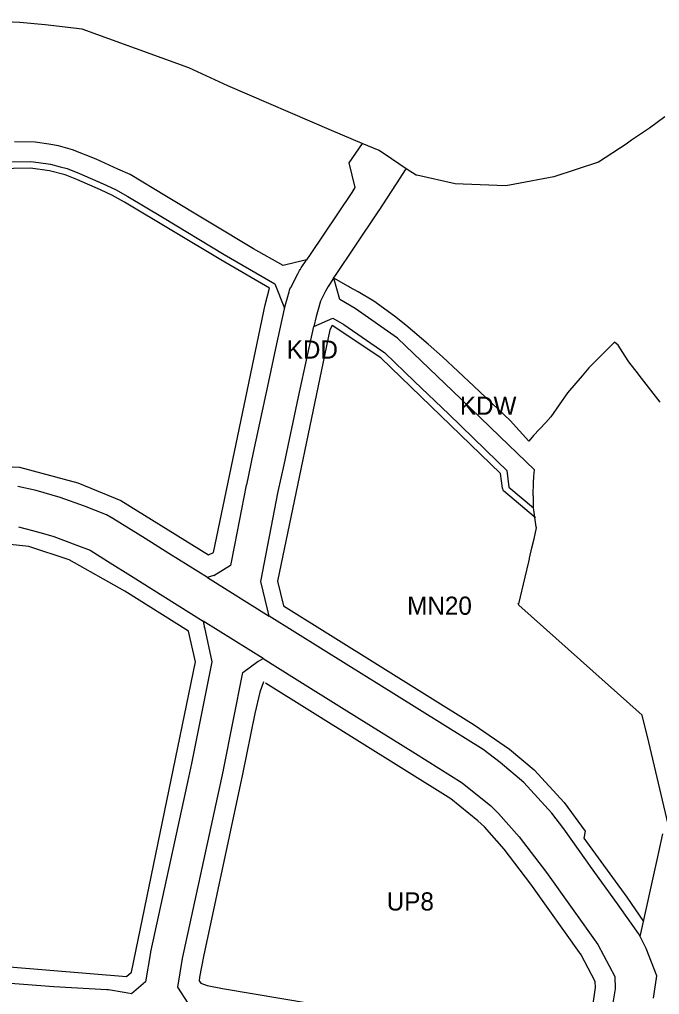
# Model space of a CAD drawing. Extents: x 7428080 to 7432143, y 5545880 to 5549217.
# Drawn here: x 7430729.6 to 7430925.4, y 5547441.7 to 5547739.8 of the extents above; entities that cross this region are included whole.
import ezdxf

# ---------------------------------------------------------------- set-up
doc = ezdxf.new("R2010")
doc.units = 0
for name, color, linetype in [('CZ_L_linie rozgraniczające tereny o różnym przeznaczeniu oraz różnych warunkach ich zabudowy i zagospodarowania', 7, 'Continuous'), ('CZ_L_maksymalne nieprzekraczalne linie zabudowy', 7, 'Continuous'), ('CZ_L_opisy_linie rozgraniczające tereny o różnym przeznaczeniu oraz różnych warunkach ich zabudowy i zagospodarowania', 7, 'Continuous')]:
    doc.layers.add(name, color=color, linetype=linetype)

msp = doc.modelspace()

# ---------------------------------------------------------------- linework, layer by layer
at = {"layer": 'CZ_L_linie rozgraniczające tereny o różnym przeznaczeniu oraz różnych warunkach ich zabudowy i zagospodarowania'}
for p, q in [((7430729.73, 5547738.83), (7430708.44, 5547739.76)), ((7430737.45, 5547738.17), (7430729.73, 5547738.83)), ((7430748.78, 5547736.77), (7430737.45, 5547738.17)), ((7430781.41, 5547725.02), (7430748.78, 5547736.77)), ((7430793.36, 5547719.53), (7430781.41, 5547725.02)), ((7430825.02, 5547705.84), (7430793.36, 5547719.53)), ((7430927.02, 5547710), (7430922.34, 5547706.55)), ((7430834.43, 5547701.88), (7430825.02, 5547705.84)), ((7430918.68, 5547704.09), (7430916.85, 5547702.86)), ((7430922.34, 5547706.55), (7430918.68, 5547704.09)), ((7430734.35, 5547702.22), (7430728.1, 5547702.36)), ((7430738.51, 5547701.68), (7430734.35, 5547702.22)), ((7430741.5, 5547701.1), (7430738.51, 5547701.68)), ((7430745.84, 5547699.95), (7430741.5, 5547701.1)), ((7430834.43, 5547701.88), (7430830.29, 5547695.93)), ((7430839.61, 5547699.7), (7430834.43, 5547701.88)), ((7430915.14, 5547701.62), (7430906.73, 5547696.19)), ((7430916.85, 5547702.86), (7430915.14, 5547701.62)), ((7430753.07, 5547697.04), (7430745.84, 5547699.95)), ((7430843.36, 5547697.14), (7430839.61, 5547699.7)), ((7430726.23, 5547696.23), (7430733.01, 5547696.31)), ((7430733.01, 5547696.31), (7430735.43, 5547696.03)), ((7430735.43, 5547696.03), (7430739.1, 5547695.5)), ((7430739.1, 5547695.5), (7430742.02, 5547694.75)), ((7430742.02, 5547694.75), (7430744.16, 5547694.17)), ((7430759.67, 5547694.03), (7430753.07, 5547697.04)), ((7430830.29, 5547695.93), (7430832.2, 5547688.37)), ((7430847.84, 5547694.08), (7430843.36, 5547697.14)), ((7430906.73, 5547696.19), (7430893.07, 5547691.66)), ((7430744.16, 5547694.17), (7430747.93, 5547692.68)), ((7430747.93, 5547692.68), (7430755.18, 5547689.56)), ((7430763.41, 5547692.39), (7430759.67, 5547694.03)), ((7430774.54, 5547685.65), (7430763.41, 5547692.39)), ((7430845.99, 5547691.22), (7430847.69, 5547693.83)), ((7430847.69, 5547693.83), (7430847.76, 5547693.95)), ((7430847.76, 5547693.95), (7430847.84, 5547694.08)), ((7430850.92, 5547692.22), (7430847.84, 5547694.08)), ((7430851.09, 5547692.18), (7430850.92, 5547692.22)), ((7430862.83, 5547689.49), (7430851.09, 5547692.18)), ((7430755.18, 5547689.56), (7430758.91, 5547687.79)), ((7430839.59, 5547681.38), (7430845.99, 5547691.22)), ((7430865.29, 5547689.42), (7430862.83, 5547689.49)), ((7430878.33, 5547688.95), (7430865.29, 5547689.42)), ((7430881.13, 5547689.47), (7430878.33, 5547688.95)), ((7430893.07, 5547691.66), (7430881.13, 5547689.47)), ((7430758.91, 5547687.79), (7430762.75, 5547685.63)), ((7430831.23, 5547686.87), (7430822.68, 5547674.16)), ((7430832.2, 5547688.37), (7430831.23, 5547686.87)), ((7430762.75, 5547685.63), (7430773.3, 5547679.32)), ((7430801.19, 5547669.63), (7430774.54, 5547685.65)), ((7430832.05, 5547670.17), (7430839.55, 5547681.32)), ((7430839.55, 5547681.32), (7430839.59, 5547681.38)), ((7430773.3, 5547679.32), (7430792.19, 5547667.97)), ((7430822.68, 5547674.16), (7430818.49, 5547667.92)), ((7430792.19, 5547667.97), (7430807.71, 5547658.97)), ((7430810.21, 5547664.55), (7430801.19, 5547669.63)), ((7430818.49, 5547667.92), (7430817.42, 5547666.33)), ((7430826.46, 5547661.85), (7430832.05, 5547670.17)), ((7430817.42, 5547666.33), (7430810.21, 5547664.55)), ((7430815.74, 5547663.83), (7430817.24, 5547666.05)), ((7430817.24, 5547666.05), (7430817.42, 5547666.33)), ((7430812.54, 5547657.89), (7430814.7, 5547662.01)), ((7430814.7, 5547662.01), (7430815.24, 5547663.03)), ((7430815.24, 5547663.03), (7430815.4, 5547663.31)), ((7430815.4, 5547663.31), (7430815.51, 5547663.49)), ((7430815.51, 5547663.49), (7430815.74, 5547663.83)), ((7430807.71, 5547658.97), (7430810.63, 5547651.51)), ((7430825.67, 5547660.68), (7430824.37, 5547658.75)), ((7430825.69, 5547660.7), (7430825.67, 5547660.68)), ((7430825.69, 5547660.7), (7430826.46, 5547661.85)), ((7430825.7, 5547660.67), (7430825.69, 5547660.7)), ((7430827.63, 5547654.13), (7430825.7, 5547660.67)), ((7430830.25, 5547658.11), (7430825.7, 5547660.67)), ((7430810.64, 5547651.56), (7430812.03, 5547656.49)), ((7430812.03, 5547656.49), (7430812.15, 5547656.91)), ((7430812.15, 5547656.91), (7430812.16, 5547656.98)), ((7430812.16, 5547656.98), (7430812.27, 5547657.29)), ((7430812.27, 5547657.29), (7430812.39, 5547657.59)), ((7430812.39, 5547657.59), (7430812.53, 5547657.88)), ((7430812.53, 5547657.88), (7430812.54, 5547657.89)), ((7430823.22, 5547656.72), (7430821.63, 5547653.7)), ((7430823.96, 5547658.14), (7430823.22, 5547656.72)), ((7430824.37, 5547658.75), (7430823.96, 5547658.14)), ((7430830.5, 5547657.97), (7430830.25, 5547658.11)), ((7430833.14, 5547656.49), (7430830.5, 5547657.97)), ((7430837.95, 5547653.68), (7430833.14, 5547656.49)), ((7430821.63, 5547653.7), (7430820.91, 5547651.14)), ((7430832.32, 5547651.38), (7430827.63, 5547654.13)), ((7430844.29, 5547649.06), (7430837.95, 5547653.68)), ((7430810.58, 5547651.29), (7430807.89, 5547639.2)), ((7430810.63, 5547651.51), (7430810.58, 5547651.3)), ((7430810.58, 5547651.3), (7430810.58, 5547651.29)), ((7430810.63, 5547651.51), (7430810.64, 5547651.56)), ((7430820.91, 5547651.14), (7430820.31, 5547648.98)), ((7430845.22, 5547642.4), (7430832.32, 5547651.38)), ((7430820.31, 5547648.98), (7430819.63, 5547645.93)), ((7430819.63, 5547645.93), (7430825.41, 5547648.49)), ((7430825.41, 5547648.49), (7430828.78, 5547646.5)), ((7430847.79, 5547646.28), (7430844.29, 5547649.06)), ((7430817.66, 5547637.05), (7430819.63, 5547645.93)), ((7430828.78, 5547646.5), (7430841.35, 5547637.87)), ((7430854.62, 5547640.52), (7430847.79, 5547646.28)), ((7430864.64, 5547623.83), (7430845.22, 5547642.4)), ((7430911.56, 5547641.17), (7430903.76, 5547633.29)), ((7430912.72, 5547640.19), (7430911.56, 5547641.17)), ((7430807.88, 5547639.16), (7430805.74, 5547629.14)), ((7430807.89, 5547639.2), (7430807.88, 5547639.16)), ((7430859.02, 5547636.64), (7430854.62, 5547640.52)), ((7430914.84, 5547636.88), (7430912.72, 5547640.19)), ((7430814.95, 5547624.42), (7430817.66, 5547637.05)), ((7430841.35, 5547637.87), (7430850.47, 5547629.16)), ((7430868.58, 5547627.72), (7430859.02, 5547636.64)), ((7430915.98, 5547635.1), (7430914.84, 5547636.88)), ((7430903.76, 5547633.29), (7430901.69, 5547630.82)), ((7430918.93, 5547631.32), (7430915.98, 5547635.1)), ((7430850.47, 5547629.16), (7430860.93, 5547619.09)), ((7430901.69, 5547630.82), (7430897.21, 5547625.69)), ((7430919.13, 5547631.07), (7430918.93, 5547631.32)), ((7430925.59, 5547622.81), (7430919.13, 5547631.07)), ((7430805.74, 5547629.14), (7430801.09, 5547607.43)), ((7430879.64, 5547617.23), (7430868.58, 5547627.72)), ((7430810.51, 5547603.67), (7430814.95, 5547624.42)), ((7430876.49, 5547612.32), (7430864.64, 5547623.83)), ((7430897.21, 5547625.69), (7430892.14, 5547618.29)), ((7430860.93, 5547619.09), (7430875.85, 5547604.61)), ((7430892.14, 5547618.29), (7430890.6, 5547616.56)), ((7430885.42, 5547610.89), (7430879.64, 5547617.23)), ((7430890.6, 5547616.56), (7430886.83, 5547612.64)), ((7430887.12, 5547602.16), (7430876.49, 5547612.32)), ((7430886.83, 5547612.64), (7430885.42, 5547610.89)), ((7430801.09, 5547607.43), (7430798.98, 5547597.56)), ((7430808.76, 5547595.51), (7430810.51, 5547603.67)), ((7430875.85, 5547604.61), (7430878.67, 5547601.9)), ((7430878.67, 5547601.9), (7430879.29, 5547596.84)), ((7430886.83, 5547597.91), (7430886.89, 5547600.3)), ((7430886.89, 5547600.3), (7430886.99, 5547601.11)), ((7430886.99, 5547601.11), (7430887.12, 5547602.16)), ((7430734.68, 5547595.76), (7430729.05, 5547596.99)), ((7430798.96, 5547597.47), (7430795.38, 5547579.08)), ((7430798.98, 5547597.56), (7430798.96, 5547597.47)), ((7430879.29, 5547596.84), (7430886.86, 5547590.49)), ((7430886.76, 5547594.71), (7430886.83, 5547597.91)), ((7430742.03, 5547593.68), (7430734.68, 5547595.76)), ((7430749.46, 5547591.05), (7430742.03, 5547593.68)), ((7430803.41, 5547567.95), (7430808.76, 5547595.51)), ((7430886.75, 5547594.2), (7430886.76, 5547594.71)), ((7430886.79, 5547594.16), (7430886.75, 5547594.2)), ((7430886.85, 5547590.56), (7430886.79, 5547594.16)), ((7430756.18, 5547588.34), (7430749.46, 5547591.05)), ((7430886.86, 5547590.49), (7430886.85, 5547590.56)), ((7430887.68, 5547584.71), (7430886.86, 5547590.49)), ((7430758.13, 5547587.26), (7430756.18, 5547588.34)), ((7430729.3, 5547584.64), (7430733.54, 5547583.61)), ((7430767.99, 5547581.16), (7430758.13, 5547587.26)), ((7430887.74, 5547584.37), (7430887.68, 5547584.71)), ((7430733.54, 5547583.61), (7430736.97, 5547582.7)), ((7430736.97, 5547582.7), (7430740.07, 5547581.7)), ((7430740.07, 5547581.7), (7430746.8, 5547579.18)), ((7430886.99, 5547581.06), (7430887.74, 5547584.36)), ((7430887.74, 5547584.36), (7430887.74, 5547584.37)), ((7430746.8, 5547579.18), (7430751.25, 5547577.55)), ((7430775.29, 5547576.56), (7430767.99, 5547581.16)), ((7430795.38, 5547579.08), (7430794.18, 5547572.89)), ((7430886.35, 5547578.28), (7430886.99, 5547581.06)), ((7430751.25, 5547577.55), (7430756.55, 5547574.2)), ((7430787.14, 5547569.17), (7430775.29, 5547576.56)), ((7430885.64, 5547575.16), (7430886.35, 5547578.28)), ((7430756.55, 5547574.2), (7430764.31, 5547569.3)), ((7430794.18, 5547572.89), (7430789.02, 5547569.76)), ((7430884.28, 5547569.29), (7430885.35, 5547573.96)), ((7430885.35, 5547573.96), (7430885.57, 5547574.94)), ((7430885.57, 5547574.94), (7430885.59, 5547574.95)), ((7430885.59, 5547574.95), (7430885.64, 5547575.16)), ((7430788.91, 5547569.84), (7430787.14, 5547569.17)), ((7430789.02, 5547569.76), (7430788.91, 5547569.84)), ((7430764.31, 5547569.3), (7430769.86, 5547565.81)), ((7430787.14, 5547569.17), (7430805.98, 5547557.42)), ((7430805.43, 5547559.54), (7430803.41, 5547567.95)), ((7430882.32, 5547561.19), (7430884.28, 5547569.29)), ((7430769.86, 5547565.81), (7430785.79, 5547555.87)), ((7430882.36, 5547560.78), (7430882.17, 5547561.27)), ((7430882.17, 5547561.27), (7430882.32, 5547561.19)), ((7430920.08, 5547527.17), (7430882.36, 5547560.78)), ((7430805.46, 5547559.52), (7430805.43, 5547559.54)), ((7430805.98, 5547557.42), (7430805.46, 5547559.52)), ((7430804.08, 5547544.47), (7430785.79, 5547555.87)), ((7430785.79, 5547555.87), (7430786.19, 5547553.85)), ((7430829.49, 5547542.76), (7430805.98, 5547557.42)), ((7430786.19, 5547553.85), (7430786.15, 5547553.88)), ((7430786.15, 5547553.88), (7430788.39, 5547543.45)), ((7430788.39, 5547543.45), (7430782.17, 5547512.39)), ((7430797.92, 5547540.13), (7430802.63, 5547543.61)), ((7430802.63, 5547543.61), (7430802.67, 5547543.58)), ((7430802.67, 5547543.58), (7430804.08, 5547544.47)), ((7430804.08, 5547544.47), (7430813.7, 5547538.47)), ((7430844.89, 5547533.16), (7430829.49, 5547542.76)), ((7430791.97, 5547510.38), (7430797.92, 5547540.13)), ((7430813.7, 5547538.47), (7430828.91, 5547528.99)), ((7430866.06, 5547519.96), (7430844.89, 5547533.16)), ((7430828.91, 5547528.99), (7430850.76, 5547515.36)), ((7430922.07, 5547518.83), (7430920.08, 5547527.17)), ((7430871.38, 5547516.65), (7430866.06, 5547519.96)), ((7430876.63, 5547512.66), (7430871.38, 5547516.65)), ((7430928.41, 5547492.11), (7430922.07, 5547518.83)), ((7430850.76, 5547515.36), (7430865, 5547506.48)), ((7430779.49, 5547452.79), (7430791.95, 5547510.31)), ((7430782.17, 5547512.39), (7430781.24, 5547508.09)), ((7430791.95, 5547510.31), (7430791.97, 5547510.38)), ((7430883.82, 5547506.57), (7430876.63, 5547512.66)), ((7430781.24, 5547508.09), (7430776.97, 5547488.4)), ((7430865, 5547506.48), (7430873.78, 5547499.38)), ((7430892.4, 5547497.21), (7430883.82, 5547506.57)), ((7430873.78, 5547499.38), (7430876.16, 5547497.11)), ((7430876.16, 5547497.11), (7430882.44, 5547489.95)), ((7430896.15, 5547492.4), (7430892.4, 5547497.21)), ((7430902.87, 5547482.87), (7430896.15, 5547492.4)), ((7430882.44, 5547489.95), (7430890.85, 5547479.01)), ((7430925.17, 5547485.2), (7430926.44, 5547490.87)), ((7430776.97, 5547488.4), (7430769.69, 5547454.79)), ((7430919.44, 5547459.45), (7430924.86, 5547483.79)), ((7430924.86, 5547483.79), (7430925.17, 5547485.2)), ((7430904.26, 5547480.89), (7430902.87, 5547482.87)), ((7430912.51, 5547469.44), (7430904.26, 5547480.89)), ((7430890.85, 5547479.01), (7430906.5, 5547457.01)), ((7430914.96, 5547466.03), (7430912.51, 5547469.44)), ((7430918.98, 5547460.35), (7430914.96, 5547466.03)), ((7430919.44, 5547459.45), (7430918.98, 5547460.35)), ((7430921.29, 5547455.79), (7430919.44, 5547459.45)), ((7430906.5, 5547457.01), (7430911.7, 5547447.28)), ((7430769.64, 5547454.55), (7430768.16, 5547445.64)), ((7430769.69, 5547454.79), (7430769.64, 5547454.55)), ((7430924.59, 5547447.41), (7430921.29, 5547455.79)), ((7430778.02, 5547444.03), (7430779.49, 5547452.79)), ((7430923.49, 5547440.65), (7430924.59, 5547447.41)), ((7430740.06, 5547444.05), (7430714.93, 5547446.02)), ((7430768.16, 5547445.64), (7430763.83, 5547441.99)), ((7430911.7, 5547447.28), (7430911.79, 5547443.46)), ((7430756.33, 5547443.21), (7430740.06, 5547444.05)), ((7430756.46, 5547443.2), (7430756.33, 5547443.21)), ((7430756.78, 5547443.16), (7430756.46, 5547443.2)), ((7430756.83, 5547443.15), (7430756.78, 5547443.16)), ((7430761.65, 5547442.35), (7430756.83, 5547443.15)), ((7430763.83, 5547441.99), (7430761.65, 5547442.35)), ((7430781.17, 5547439.11), (7430778.02, 5547444.03)), ((7430911.79, 5547443.46), (7430910.38, 5547434.78))]:
    msp.add_line(p, q, dxfattribs=at)
at = {"layer": 'CZ_L_maksymalne nieprzekraczalne linie zabudowy'}
for points in [[(7430787.39, 5547576.09), (7430788.89, 5547576.88), (7430804.7, 5547652.52), (7430806.1, 5547657.59), (7430791.16, 5547666.25), (7430761.74, 5547683.9), (7430757.99, 5547686.01), (7430754.35, 5547687.74), (7430747.17, 5547690.83), (7430743.53, 5547692.27), (7430738.71, 5547693.54), (7430732.9, 5547694.31), (7430717.18, 5547694.05)], [(7430887.39, 5547587.41), (7430877.68, 5547595.65), (7430877.32, 5547596.5), (7430876.77, 5547600.95), (7430840.09, 5547636.31), (7430825.21, 5547646.22), (7430824.52, 5547644.91), (7430808.53, 5547568.04), (7430810.35, 5547560.59), (7430868.71, 5547524.2), (7430879.51, 5547516.75), (7430887.05, 5547510.38), (7430896.24, 5547500.41), (7430902.59, 5547491.66), (7430902.25, 5547489.57), (7430915.34, 5547471.5), (7430920.47, 5547464.1)], [(7430718.07, 5547603.39), (7430729.59, 5547602.97), (7430747.44, 5547598.12), (7430760.56, 5547592.74), (7430787.39, 5547576.09)], [(7430762.36, 5547447.29), (7430763.84, 5547448.54), (7430783.45, 5547543.43), (7430781.33, 5547552.76), (7430761.76, 5547565), (7430744.76, 5547574.59), (7430732.48, 5547578.69), (7430717.1, 5547580.27), (7430679.42, 5547578.62), (7430616.34, 5547573.27), (7430615.14, 5547573.32), (7430605.2, 5547574.95), (7430594.21, 5547576.42), (7430582.49, 5547574.81), (7430578.9, 5547571.26), (7430578.47, 5547567.46), (7430648.83, 5547467.19), (7430652.37, 5547455.77), (7430656.58, 5547451.53), (7430689.39, 5547453.26), (7430762.36, 5547447.29)], [(7430804.2, 5547537.31), (7430803.13, 5547534.19), (7430801.59, 5547527.59), (7430797.83, 5547509.09), (7430785.86, 5547453.37), (7430784.67, 5547447.03), (7430784.56, 5547445.94), (7430785.01, 5547445.21), (7430787.01, 5547444.52), (7430791.64, 5547443.59), (7430837.04, 5547435.92)], [(7430903, 5547424.51), (7430905.78, 5547443.88), (7430905.74, 5547445.71), (7430901.39, 5547453.84), (7430886.03, 5547475.44), (7430877.81, 5547486.14), (7430871.82, 5547492.95), (7430869.81, 5547494.87), (7430861.52, 5547501.58), (7430804.83, 5547536.93)]]:
    msp.add_lwpolyline(points, dxfattribs=at)

# ---------------------------------------------------------------- texts
at = {"layer": 'CZ_L_opisy_linie rozgraniczające tereny o różnym przeznaczeniu oraz różnych warunkach ich zabudowy i zagospodarowania'}
for s, p in [('KDD', (7430811.33, 5547636.11)), ('KDW', (7430864.3, 5547618.94)), ('MN20', (7430848.18, 5547557.81)), ('UP8', (7430841.92, 5547467.42))]:
    msp.add_text(s, height=5.549, dxfattribs=at).set_placement(p)

doc.saveas('drawing.dxf')
